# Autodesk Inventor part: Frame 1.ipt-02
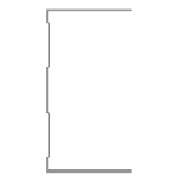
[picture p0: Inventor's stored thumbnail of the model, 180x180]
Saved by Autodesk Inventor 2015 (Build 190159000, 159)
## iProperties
IsCustomPart: 1
Created: 2015-04
Part Number: Frame 1.ipt-02
Material: Aluminum 6061
Description: Kévin Novo
Document SubType Name: Modeling
Standard: Kevin
Designer: suporte
Standards Organization: Kevin
Language: en-US
Size Designation: (Unnamed 2)
Categories: <MemberInstance><Categories><Category DisplayName="Structural Shapes" InternalName="089c4875-fa83-4c05-b084-43b9cc11f5ed" Mnemonic="GRDR"><CategoryParameter Dis
Density: 2.7 g/cm^3
Appearance: Aluminum - Flat
_CCFamilyMember: 2
_CCFamilyDisplayName: Kévin - Kévin Novo
_FrameMemberDoc: Frame Member File
_Version: 15.0.0
_GetPNFromCC: 1
G_W: 50,000 mm
G_H: 75,000 mm
G_L: 2100,000 mm
+DCBF74A3-3B5E-4998-AEE0-6409F6B46BA7+CUTDETAIL1: Notch
+70756B77-2A19-4D14-8474-32D11EDA9B5F+CUTDETAIL2: Notch
Author: suporte
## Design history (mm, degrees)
node "Start Plane"
node "End Plane"
sketch "Sketch"
  geometry: L1 (24.7, 37.5)-(24.7, 36.9); L2 (24.7, 36.9)-(-24.7, 36.9); L3 (-24.7, -36.9)-(24.7, -36.9); L4 (24.7, -36.9)-(24.7, -37.5); L5 (24.7, -37.5)-(-25.3, -37.5); L6 (-25.3, 37.5)-(24.7, 37.5); L7 (-24.7, 36.9)-(-24.7, 31.9); L8 (-24.7, 31.9)-(-23.3, 30.5); L9 (-23.3, 30.5)-(-23.3, 10.934); L10 (-23.3, 10.934)-(-24.7, 9.534); L11 (-24.7, 9.534)-(-24.7, -9.534); L12 (-24.7, -9.534)-(-23.3, -10.934); L13 (-23.3, -10.934)-(-23.3, -30.5); L14 (-23.3, -30.5)-(-24.7, -31.9); L15 (-24.7, -31.9)-(-24.7, -36.9); L16 (-25.3, -37.5)-(-25.3, -31.651); L17 (-25.3, -31.651)-(-23.9, -30.251); L18 (-23.9, -30.251)-(-23.9, -11.183); L19 (-23.9, -11.183)-(-25.3, -9.783); L20 (-25.3, -9.783)-(-25.3, 9.783); L21 (-25.3, 9.783)-(-23.9, 11.183); L22 (-23.9, 11.183)-(-23.9, 30.251); L23 (-23.9, 30.251)-(-25.3, 31.651); L24 (-25.3, 31.651)-(-25.3, 37.5); L25 (-25.3, 0)-(30.37, 0); 3 further points
  constraints: 50 end point, 10 point on line, 9 parallel, 5 perpendicular, 4 equal length, 3 midpoint, 3 vertical, 2 vertical alignment, 1 collinear, 1 horizontal, 1 horizontal alignment
  dimensions: "d3" = 0.6 distance of L1.start L1.end (= d6); "d5" = 75 distance between parallel lines of L5 L6; "d6" = 0.6 distance between parallel lines of L24 L7 (= d8); "d7" = 0.6 distance between parallel lines of L8 L23 (= d8); "d8" = 0.6 distance between parallel lines of L22 L9 (= d12); "Espessura" = 0.6 distance between parallel lines of L17 L14; "d10" = 0.6 distance between parallel lines of L13 L18 (= Espessura); "d11" = 0.6 distance between parallel lines of L12 L19 (= Espessura); "d12" = 0.6 distance between parallel lines of L21 L10 (= d11); "d13" = 5 distance of L2.end L7.end; "d15" = 135 deg angle of L9 L8; "d16" = 2 distance between parallel lines of L24 L9; "d17" = 50 distance of L6.start L1.start
extrude "Body" join sketch "Sketch" stored distance "d24" = 0.13; taper "d25" = 0 deg
node "Driven Length"
  sketch "Sketch10"
    geometry: L1 (0, 0)-(10, 0) reference
    constraints: 2 end point, 1 horizontal
  workplane "Work Plane7"
  sketch "Sketch11"
    geometry: L1 (-2, 0)-(12, 0) reference; L2 (-2, 2100)-(12, 2100) reference
    dimensions: "d27" = 2100 distance between parallel lines of L1 L2 (derived)
workplane "Work Plane8"
workplane "Work Plane9"
workplane "Work Plane10"
sketch "Sketch12"
  geometry: L1 (24.7, 37.5)-(24.7, 36.9); L2 (24.7, 36.9)-(-24.7, 36.9); L3 (-24.7, 36.9)-(-24.7, 31.9); L4 (-24.7, 31.9)-(-23.3, 30.5); L5 (-23.3, 30.5)-(-23.3, 10.934); L6 (-23.3, 10.934)-(-24.7, 9.534); L7 (-24.7, 9.534)-(-24.7, -9.534); L8 (-24.7, -9.534)-(-23.3, -10.934); L9 (-23.3, -10.934)-(-23.3, -30.5); L10 (-23.3, -30.5)-(-24.7, -31.9); L11 (-24.7, -31.9)-(-24.7, -36.9); L12 (-24.7, -36.9)-(24.7, -36.9); L13 (24.7, -36.9)-(24.7, -37.5); L14 (24.7, -37.5)-(-25.3, -37.5); L15 (-25.3, -37.5)-(-25.3, -31.651); L16 (-25.3, -31.651)-(-23.9, -30.251); L17 (-23.9, -30.251)-(-23.9, -11.183); L18 (-23.9, -11.183)-(-25.3, -9.783); L19 (-25.3, -9.783)-(-25.3, 9.783); L20 (-25.3, 9.783)-(-23.9, 11.183); L21 (-23.9, 11.183)-(-23.9, 30.251); L22 (-23.9, 30.251)-(-25.3, 31.651); L23 (-25.3, 31.651)-(-25.3, 37.5); L24 (-25.3, 37.5)-(24.7, 37.5)
  constraints: 48 end point, 10 point on line
extrude "Extrusion3" cut sketch "Sketch12" stored distance "d36" = 0.13; taper "d37" = 0 deg
workplane "Work Plane11"
workplane "Work Plane12"
workplane "Work Plane13"
sketch "Sketch13"
  geometry: L1 (24.7, 37.5)-(24.7, 36.9); L2 (24.7, 36.9)-(-24.7, 36.9); L3 (-24.7, 36.9)-(-24.7, 31.9); L4 (-24.7, 31.9)-(-23.3, 30.5); L5 (-23.3, 30.5)-(-23.3, 10.934); L6 (-23.3, 10.934)-(-24.7, 9.534); L7 (-24.7, 9.534)-(-24.7, -9.534); L8 (-24.7, -9.534)-(-23.3, -10.934); L9 (-23.3, -10.934)-(-23.3, -30.5); L10 (-23.3, -30.5)-(-24.7, -31.9); L11 (-24.7, -31.9)-(-24.7, -36.9); L12 (-24.7, -36.9)-(24.7, -36.9); L13 (24.7, -36.9)-(24.7, -37.5); L14 (24.7, -37.5)-(-25.3, -37.5); L15 (-25.3, -37.5)-(-25.3, -31.651); L16 (-25.3, -31.651)-(-23.9, -30.251); L17 (-23.9, -30.251)-(-23.9, -11.183); L18 (-23.9, -11.183)-(-25.3, -9.783); L19 (-25.3, -9.783)-(-25.3, 9.783); L20 (-25.3, 9.783)-(-23.9, 11.183); L21 (-23.9, 11.183)-(-23.9, 30.251); L22 (-23.9, 30.251)-(-25.3, 31.651); L23 (-25.3, 31.651)-(-25.3, 37.5); L24 (-25.3, 37.5)-(24.7, 37.5)
  constraints: 48 end point, 10 point on line
extrude "Extrusion4" cut sketch "Sketch13" stored distance "d38" = 0.13; taper "d39" = 0 deg
body "Solid1"
other parameters: "G_OFFSET_START" = 0 [user parameter; used in 1 equation term], "G_OFFSET_END" = 0 [user parameter; used in 1 equation term], "d22" = 0 (computed from G_OFFSET_START), "G_L" = 2100 (= d27) [user parameter], "d34" = 90 deg
